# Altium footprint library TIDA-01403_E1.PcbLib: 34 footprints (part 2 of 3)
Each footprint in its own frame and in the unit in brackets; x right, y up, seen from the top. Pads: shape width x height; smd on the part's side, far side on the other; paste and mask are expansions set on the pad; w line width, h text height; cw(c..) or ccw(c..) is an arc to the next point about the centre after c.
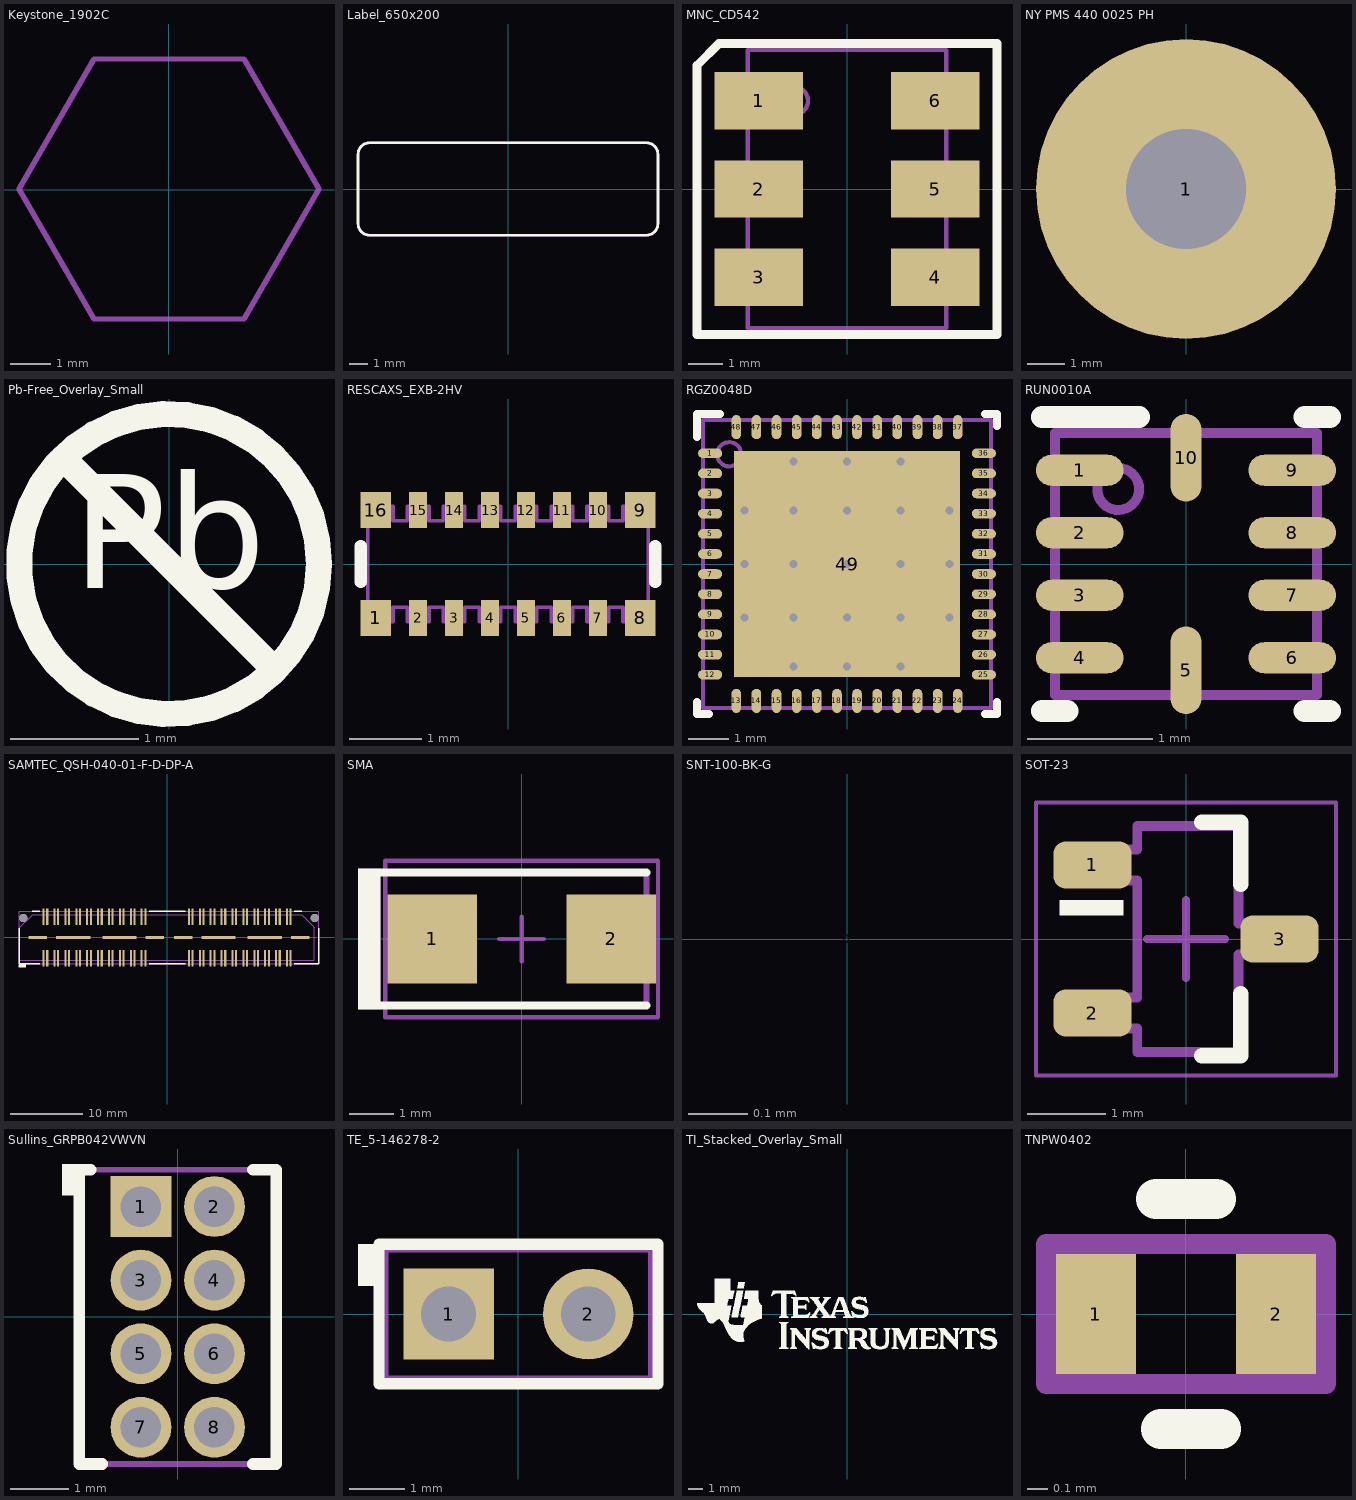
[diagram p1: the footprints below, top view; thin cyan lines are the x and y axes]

## Keystone_1902C [mm] "Hex Standoff, 4-40 threaded, nylon"
height 12.7
Mechanical 5:
  lines w0.127: -3.69,0.012 -1.843,-3.188 1.852,-3.188 3.7,0.012 1.852,3.212 -1.843,3.212 -3.69,0.012
  text ".Designator" at -1.524,-0.508 h0.76
3D body: height 12.73, standoff 0.03, extent -3.682,-3.2 3.708,3.2

## Label_650x200 [mm] "Thermal Transfer Label"
height 0.025
Top Overlay:
  lines w0.152: -8.255,-1.905 ccw(c-7.62,-1.905) -7.62,-2.54 7.62,-2.54 ccw(c7.62,-1.905) 8.255,-1.905 8.255,1.905 ccw(c7.62,1.905) 7.62,2.54 -7.62,2.54 ccw(c-7.62,1.905) -8.255,1.905 -8.255,-1.905
Mechanical 5:
  lines w0.127: -8.255,-1.905 ccw(c-7.62,-1.905) -7.62,-2.54 7.62,-2.54 ccw(c7.62,-1.905) 8.255,-1.905 8.255,1.905 ccw(c7.62,1.905) 7.62,2.54 -7.62,2.54 ccw(c-7.62,1.905) -8.255,1.905 -8.255,-1.905
  text ".Designator" at -1.524,-0.508 h0.64
3D body: height 0.03, standoff 0, extent -8.268,-2.553 8.268,2.553

## MNC_CD542 [mil] "Mini-Circuits recommended land pattern 98-CD.doc rev K 11/06/06"
height 112
pads (6):
  rect 100x65 smd: 1(-100,100) 2(-100,0) 3(-100,-100) 4(100,-100) 5(100,0) 6(100,100)
Top Overlay:
  lines w10: -170,-165 0,-165 170,-165 170,0 170,165 0,165 -145,165 -170,140 -170,0 -170,-165
Mechanical 5:
  circle w5: c-60,100 r15.81
  lines w5: -112.5,-115 -141,-115 -141,-85 -112.5,-85 ; -112.5,-15 -141,-15 -141,15 -112.5,15 ; -112.5,85 -141,85 -141,115 -112.5,115 ; 112.5,-115 141,-115 141,-85 112.5,-85 ; 112.5,-15 141,-15 141,15 112.5,15 ; 112.5,85 141,85 141,115 112.5,115 ; -112.5,-157.5 -112.5,0 -112.5,157.5 0,157.5 112.5,157.5 112.5,0 112.5,-157.5 0,-157.5 -112.5,-157.5
  text ".Designator" at 9,-22 h25
3D body: height 10, standoff 0, extent 112.52,85.02 140.98,114.98
3D body: height 10, standoff 0, extent 112.52,-14.98 140.98,14.98
3D body: height 10, standoff 0, extent 112.52,-114.98 140.98,-85.02
3D body: height 10, standoff 0, extent -140.98,85.02 -112.52,114.98
3D body: height 112, standoff 0, extent -112.48,-157.48 112.48,157.48
3D body: height 10, standoff 0, extent -140.98,-14.98 -112.52,14.98
3D body: height 10, standoff 0, extent -140.98,-114.98 -112.52,-85.02
3D body: height 112.01, standoff 110, extent -76.1,83.9 -43.9,116.1

## NY PMS 440 0025 PH [mm] "4-40 nylon screw and mounting hole"
height 1.905
pads (1):
  round 8 hole 3.2: 1(0,0)
Mechanical 5:
  circle w0.127: c0,0 r3.789
  text ".Designator" at -1.524,-0.508 h0.64
3D body: height 2.69, standoff -8.74, extent -3.302,-3.3 3.296,3.3

## Pb-Free_Overlay_Small [mm]
Top Overlay:
  circle w0.203: c0,0 r1.168
  lines w0.203: -0.826,0.826 0.826,-0.826
  text "Pb" at -0.752,-0.48 h1.52

## RESCAXS_EXB-2HV [mm] "Panasonic Resistor Array"
height 0.55
pads (16):
  rect 0.425x0.5 smd mask+0.07: 1(-1.837,-0.75) 8(1.837,-0.75) 9(1.837,0.75) 16(-1.837,0.75)
  rect 0.25x0.5 smd mask+0.07: 2(-1.25,-0.75) 3(-0.75,-0.75) 4(-0.25,-0.75) 5(0.25,-0.75) 6(0.75,-0.75) 7(1.25,-0.75) 10(1.25,0.75) 11(0.75,0.75) 12(0.25,0.75) 13(-0.25,0.75) 14(-0.75,0.75) 15(-1.25,0.75)
Top Overlay:
  lines w0.17: -2.05,-0.25 -2.05,0.25 ; 2.05,-0.25 2.05,0.25
Mechanical 5:
  lines w0.05: -1.95,-0.8 -1.95,0.8 -1.6,0.8 -1.6,0.6 -1.4,0.6 -1.4,0.8 -1.1,0.8 -1.1,0.6 -0.9,0.6 -0.9,0.8 -0.6,0.8 -0.6,0.6 -0.4,0.6 -0.4,0.8 -0.1,0.8 -0.1,0.6 0.1,0.6 0.1,0.8 0.4,0.8 0.4,0.6 0.6,0.6 0.6,0.8 0.9,0.8 0.9,0.6 1.1,0.6 1.1,0.8 1.4,0.8 1.4,0.6 1.6,0.6 1.6,0.8 1.95,0.8 1.95,-0.8 1.6,-0.8 1.6,-0.6 1.4,-0.6 1.4,-0.8 1.1,-0.8 1.1,-0.6 0.9,-0.6 0.9,-0.8 0.6,-0.8 0.6,-0.6 0.4,-0.6 0.4,-0.8 0.1,-0.8 0.1,-0.6 -0.1,-0.6 -0.1,-0.8 -0.4,-0.8 -0.4,-0.6 -0.6,-0.6 -0.6,-0.8 -0.9,-0.8 -0.9,-0.6 -1.1,-0.6 -1.1,-0.8 -1.4,-0.8 -1.4,-0.6 -1.6,-0.6 -1.6,-0.8 -1.95,-0.8
  text ".Designator" at 0.864,0.356 h0.64
3D body: height 0.55, standoff 0, extent -1.949,-0.799 1.949,0.799
3D body: height 0.55, standoff 0.52, extent -1.949,-0.449 1.949,0.449

## RGZ0048D [mm] "QFN, 48-Leads, Body 7x7mm, Pitch 0.5mm, Thermal Pad 5.6x5.6mm, TI Recommended"
height 1
pads (49):
  oval 0.6x0.24 smd: 1(-3.4,2.75) 2(-3.4,2.25) 3(-3.4,1.75) 4(-3.4,1.25) 5(-3.4,0.75) 6(-3.4,0.25) 7(-3.4,-0.25) 8(-3.4,-0.75) 9(-3.4,-1.25) 10(-3.4,-1.75) 11(-3.4,-2.25) 12(-3.4,-2.75) 25(3.4,-2.75) 26(3.4,-2.25) 27(3.4,-1.75) 28(3.4,-1.25) 29(3.4,-0.75) 30(3.4,-0.25) 31(3.4,0.25) 32(3.4,0.75) 33(3.4,1.25) 34(3.4,1.75) 35(3.4,2.25) 36(3.4,2.75)
  oval 0.24x0.6 smd: 13(-2.75,-3.4) 14(-2.25,-3.4) 15(-1.75,-3.4) 16(-1.25,-3.4) 17(-0.75,-3.4) 18(-0.25,-3.4) 19(0.25,-3.4) 20(0.75,-3.4) 21(1.25,-3.4) 22(1.75,-3.4) 23(2.25,-3.4) 24(2.75,-3.4) 37(2.75,3.4) 38(2.25,3.4) 39(1.75,3.4) 40(1.25,3.4) 41(0.75,3.4) 42(0.25,3.4) 43(-0.25,3.4) 44(-0.75,3.4) 45(-1.25,3.4) 46(-1.75,3.4) 47(-2.25,3.4) 48(-2.75,3.4)
  rect 5.6x5.6 smd paste-2.8: 49(0,0)
via -2.55,0 diameter 0.5 hole 0.2
via -1.334,2.55 diameter 0.5 hole 0.2
via 0,2.55 diameter 0.5 hole 0.2
via 1.334,2.55 diameter 0.5 hole 0.2
via -2.55,1.334 diameter 0.5 hole 0.2
via -1.334,1.334 diameter 0.5 hole 0.2
via 0,1.334 diameter 0.5 hole 0.2
via 1.334,1.334 diameter 0.5 hole 0.2
via 2.55,1.334 diameter 0.5 hole 0.2
via -1.334,0 diameter 0.5 hole 0.2
via 0,0 diameter 0.5 hole 0.2
via 1.334,0 diameter 0.5 hole 0.2
via 2.55,0 diameter 0.5 hole 0.2
via -2.55,-1.334 diameter 0.5 hole 0.2
via -1.334,-1.334 diameter 0.5 hole 0.2
via 0,-1.334 diameter 0.5 hole 0.2
via 1.334,-1.334 diameter 0.5 hole 0.2
via 2.55,-1.334 diameter 0.5 hole 0.2
via -1.334,-2.55 diameter 0.5 hole 0.2
via 0,-2.55 diameter 0.5 hole 0.2
via 1.334,-2.55 diameter 0.5 hole 0.2
Top Overlay:
  lines w0.2: -3.725,-3.425 -3.725,-3.725 -3.425,-3.725 ; -3.725,3.15 -3.725,3.725 -3.15,3.725 ; 3.425,-3.725 3.725,-3.725 3.725,-3.425 ; 3.425,3.725 3.725,3.725 3.725,3.425
Top Paste:
  rectangle: 0.1,0.1 1.234,1.234
  rectangle: 1.434,0.1 2.568,1.234
  region: -1.434,1.234 -2.568,1.234 -2.568,0.1 -1.434,0.1
  region: -0.1,1.234 -1.234,1.234 -1.234,0.1 -0.1,0.1
  region: -0.1,2.568 -1.234,2.568 -1.234,1.434 -0.1,1.434
  region: -1.434,2.568 -2.568,2.568 -2.568,1.434 -1.434,1.434
  rectangle: 1.434,1.434 2.568,2.568
  rectangle: 0.1,1.434 1.234,2.568
  rectangle: 0.1,-2.568 1.234,-1.434
  rectangle: 1.434,-2.568 2.568,-1.434
  region: -1.434,-1.434 -2.568,-1.434 -2.568,-2.568 -1.434,-2.568
  region: -0.1,-1.434 -1.234,-1.434 -1.234,-2.568 -0.1,-2.568
  region: -0.1,-0.1 -1.234,-0.1 -1.234,-1.234 -0.1,-1.234
  region: -1.434,-0.1 -2.568,-0.1 -2.568,-1.234 -1.434,-1.234
  rectangle: 1.434,-1.234 2.568,-0.1
  rectangle: 0.1,-1.234 1.234,-0.1
Mechanical 5:
  circle w0.1: c-2.925,2.725 r0.3
  lines w0.1: -3.575,-3.575 -3.575,3.575 3.575,3.575 3.575,-3.575 -3.575,-3.575
  text ".Designator" at 0.076,-0.432 h0.64
3D body: height 1, standoff 0, extent -3.575,-3.575 3.575,3.575
3D body: height 1.01, standoff 0.5, extent -3.23,2.42 -2.62,3.03

## RUN0010A [mm]
height 0.8
pads (10):
  oval 0.7x0.25 smd: 1(-0.85,0.75) 2(-0.85,0.25) 3(-0.85,-0.25) 4(-0.85,-0.75) 6(0.85,-0.75) 7(0.85,-0.25) 8(0.85,0.25) 9(0.85,0.75)
  oval 0.25x0.7 smd: 5(0,-0.85) 10(0,0.85)
Top Overlay:
  lines w0.178: -1.15,-1.175 -0.95,-1.175 ; -1.15,1.175 -0.375,1.175 ; 0.95,-1.175 1.15,-1.175 ; 0.95,1.175 1.15,1.175
Mechanical 5:
  circle w0.08: c-0.543,0.6 r0.168
  lines w0.08: -1.05,-1.05 -1.05,1.05 1.05,1.05 1.05,-1.05 -1.05,-1.05
  text ".Designator" at 0.61,-0.533 h0.64
3D body: height 0.8, standoff 0, extent -1.049,-1.049 1.049,1.049
3D body: height 0.81, standoff 0.5, extent -0.713,0.43 -0.372,0.77

## SAMTEC_QSH-040-01-F-D-DP-A [mm] "SMD, 40x2 Position"
height 3.175
pads (90):
  rect 0.28x2.27 smd: 1(-17,-2.87) 2(-17,2.87) 3(-16.5,-2.87) 4(-16.5,2.87) 5(-15.5,-2.87) 6(-15.5,2.87) 7(-15,-2.87) 8(-15,2.87) 9(-14,-2.87) 10(-14,2.87) 11(-13.5,-2.87) 12(-13.5,2.87) 13(-12.5,-2.87) 14(-12.5,2.87) 15(-12,-2.87) 16(-12,2.87) 17(-11,-2.87) 18(-11,2.87) 19(-10.5,-2.87) 20(-10.5,2.87) 21(-9.5,-2.87) 22(-9.5,2.87) 23(-9,-2.87) 24(-9,2.87) 25(-8,-2.87) 26(-8,2.87) 27(-7.5,-2.87) 28(-7.5,2.87) 29(-6.5,-2.87) 30(-6.5,2.87) 31(-6,-2.87) 32(-6,2.87) 33(-5,-2.87) 34(-5,2.87) 35(-4.5,-2.87) 36(-4.5,2.87) 37(-3.5,-2.87) 38(-3.5,2.87) 39(-3,-2.87) 40(-3,2.87) 41(3,-2.87) 42(3,2.87) 43(3.5,-2.87) 44(3.5,2.87) 45(4.5,-2.87) 46(4.5,2.87) 47(5,-2.87) 48(5,2.87) 49(6,-2.87) 50(6,2.87) 51(6.5,-2.87) 52(6.5,2.87) 53(7.5,-2.87) 54(7.5,2.87) 55(8,-2.87) 56(8,2.87) 57(9,-2.87) 58(9,2.87) 59(9.5,-2.87) 60(9.5,2.87) 61(10.5,-2.87) 62(10.5,2.87) 63(11,-2.87) 64(11,2.87) 65(12,-2.87) 66(12,2.87) 67(12.5,-2.87) 68(12.5,2.87) 69(13.5,-2.87) 70(13.5,2.87) 71(14,-2.87) 72(14,2.87) 73(15,-2.87) 74(15,2.87) 75(15.5,-2.87) 76(15.5,2.87) 77(16.5,-2.87) 78(16.5,2.87) 79(17,-2.87) 80(17,2.87)
  rect 2.54x0.43 smd: 81(-17.81,0) 84(-1.69,0) 85(2.19,0) 88(18.31,0)
  rect 4.7x0.43 smd: 82(-12.93,0) 83(-6.58,0) 86(7.08,0) 87(13.43,0)
  round 1.15 hole 1.15 unplated mask+0.254: MH1(-19.81,2.67) MH2(20.326,2.67)
Top Overlay:
  region: -19.456,-4.166 -19.456,-3.694 -20.472,-3.694 -20.472,-4.166
  lines w0.178: -20.388,1.295 -20.388,-3.62 -17.529,-3.62 ; -18.542,3.62 -17.529,3.62 ; -2.471,-3.62 2.471,-3.62 ; -2.471,3.62 2.471,3.62 ; 17.529,-3.62 20.888,-3.62 20.888,1.295 ; 17.529,3.62 18.542,3.62
Mechanical 5:
  lines w0.1: -20.257,-3.109 -20.257,1.385 -18.529,3.114 18.502,3.114 20.231,1.385 20.231,-3.109 -20.257,-3.109
  lines w0.127: -20.388,-3.62 20.888,-3.62 20.888,3.62 -20.388,3.62 -20.388,-3.62
  text ".Designator" at -0.381,-0.33 h0.64
3D body: height 3.17, standoff -0.83, extent -20.419,-3.743 20.894,3.75

## SMA [mm] "Molded Diode, 2-Leads, Body 4.3x2.6mm, IPC Medium Density, based on OnSemi component dimensions and land pattern"
height 2.27
pads (2):
  rect 2x2 smd: 1(-2,0) 2(2,0)
Top Overlay:
  rectangle: -3.658,-1.575 -3.15,1.575
  lines w0.178: -3.327,-1.486 2.794,-1.486 ; -3.327,1.486 2.794,1.486
Mechanical 5:
  rectangle: -3.658,-1.575 -3.15,1.575
  lines w0.127: -3.327,-1.486 2.794,-1.486 2.794,1.486 -3.327,1.486
  text ".Designator" at -0.914,-0.356 h0.64
Mechanical 15:
  lines w0.1: -0.5,0 0.5,0 ; 0,-0.5 0,0.5 ; -3.05,-1.75 3.05,-1.75 3.05,1.75 -3.05,1.75 -3.05,-1.75
3D body: height 2.42, standoff 0.02, extent -2.6,-1.3 2.6,1.3

## SNT-100-BK-G [mil] "Samtec STEP model"
height 345
pads (1):
  round 1 on Mech3: 0(0,0)
3D body: height 344, standoff 104, extent -100,-50.05 100,50.05

## SOT-23 [mm] "SOT23, 3-Leads, Body 2.9x1.3mm, Pitch 0.95mm, Lead Span 2.5mm, IPC Medium Density"
height 1.1
pads (3):
  rrect50% 1x0.6 smd: 1(-1.2,0.95) 2(-1.2,-0.95) 3(1.2,0)
Top Overlay:
  rectangle: -1.625,0.3 -0.8,0.5
  lines w0.2: 0.2,-1.5 0.7,-1.5 0.7,-0.7 ; 0.2,1.5 0.7,1.5 0.7,0.7
Mechanical 5:
  lines w0.127: -1.16,-1.15 -1.16,-0.75 -0.625,-0.75 -0.625,0.75 -1.16,0.75 -1.16,1.15 -0.625,1.15 -0.625,1.45 0.675,1.45 0.675,0.2 1.21,0.2 1.21,-0.2 0.675,-0.2 0.675,-1.45 -0.625,-1.45 -0.625,-1.15 -1.16,-1.15
  text ".Designator" at -0.279,0.61 h0.64
Mechanical 15:
  lines w0.05: -1.925,-1.75 1.925,-1.75 1.925,1.75 -1.925,1.75 -1.925,-1.75
  lines w0.1: -0.5,0 0.5,0 ; 0,-0.5 0,0.5
3D body: height 1, standoff 0, extent -1.16,-1.45 1.21,1.45

## Sullins_GRPB042VWVN [mm] "Header, 1.27mm, 4x2, TH"
height 4
pads (8):
  rect 1.05x1.05 hole 0.7: 1(-0.635,1.905)
  round 1.05 hole 0.7: 2(0.635,1.905) 3(-0.635,0.635) 4(0.635,0.635) 5(-0.635,-0.635) 6(0.635,-0.635) 7(-0.635,-1.905) 8(0.635,-1.905)
Top Overlay:
  rectangle: -2,2.1 -1.7,2.64
  lines w0.2: -1.5,2.54 -1.7,2.54 -1.7,-2.54 -1.3,-2.54 ; 1.3,-2.54 1.7,-2.54 1.7,2.54 1.3,2.54
Mechanical 5:
  lines w0.1: -1.7,-2.54 1.7,-2.54 1.7,2.54 -1.7,2.54 -1.7,-2.54
  text ".Designator" at 0.584,0.533 h0.64
3D body: height 1, standoff 0, extent -1.699,-2.539 1.699,2.539
3D body: height 4, standoff -2.3, extent -0.835,1.705 -0.435,2.105
3D body: height 4, standoff -2.3, extent 0.435,1.705 0.835,2.105
3D body: height 4, standoff -2.3, extent 0.435,0.435 0.835,0.835
3D body: height 4, standoff -2.3, extent -0.835,0.435 -0.435,0.835
3D body: height 4, standoff -2.3, extent -0.835,-0.835 -0.435,-0.435
3D body: height 4, standoff -2.3, extent 0.435,-0.835 0.835,-0.435
3D body: height 4, standoff -2.3, extent 0.435,-2.105 0.835,-1.705
3D body: height 4, standoff -2.3, extent -0.835,-2.105 -0.435,-1.705

## TE_5-146278-2 [mm] "TE CONNECTIVITY"
height 8.128
pads (2):
  rect 1.65x1.65 hole 1: 1(-1.27,0)
  round 1.65 hole 1: 2(1.27,0)
Top Overlay:
  rectangle: -2.921,0.508 -2.54,1.27
  lines w0.203: -2.54,-1.27 2.54,-1.27 2.54,1.27 -2.54,1.27 -2.54,-1.27
Mechanical 5:
  lines w0.102: -2.413,-1.168 2.413,-1.168 2.413,1.168 -2.413,1.168 -2.413,-1.168
  text ".Designator" at 1.549,0.305 h0.64
3D body: height 2.29, standoff 0, extent -2.412,-1.168 2.412,1.168
3D body: height 8.13, standoff -3.05, extent 0.953,-0.317 1.588,0.318
3D body: height 8.13, standoff -3.05, extent -1.587,-0.317 -0.952,0.318

## TI_Stacked_Overlay_Small [mm]
Top Overlay:
  drawing of 18 lines, arcs and shapes, not listed

## TNPW0402 [mm] "Vishay"
height 0.4
pads (2):
  rect 0.4x0.6 smd: 1(-0.45,0) 2(0.45,0)
Top Overlay:
  lines w0.2: -0.15,0.575 0.15,0.575 ; -0.125,-0.575 0.175,-0.575
Mechanical 5:
  lines w0.1: -0.7,-0.35 -0.7,0.35 0.7,0.35 0.7,-0.35 -0.7,-0.35
  text ".Designator" at 1.168,-1.194 h0.64
3D body: height 0.4, standoff 0, extent 0.276,-0.274 0.524,0.274
3D body: height 0.4, standoff 0, extent -0.274,-0.274 0.274,0.274
3D body: height 0.4, standoff 0, extent -0.524,-0.274 -0.276,0.274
